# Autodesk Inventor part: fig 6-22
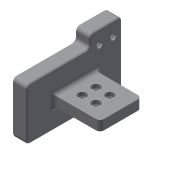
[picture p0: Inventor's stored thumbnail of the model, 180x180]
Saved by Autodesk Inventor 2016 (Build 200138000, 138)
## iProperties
Created: 2004-05
Part Number: fig 6-22
Document SubType Name: Modeling
Designer: CADCIM Technologies
Manufacturer: Standard
Standards Organization: Custom
Density: 1 g/cm^3
Material: Generic
Appearance: Default
Author: CADCIM Technologies
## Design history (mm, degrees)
node "Sketch1"
sketch "Sketch2"
  geometry: L1 (0, 0)-(0, 26.557); L2 (0, 26.557)-(31.986, 26.557); L3 (31.986, 26.557)-(31.986, 32.916); L4 (31.986, 32.916)-(48.42, 32.916); L5 (48.42, 32.916)-(48.42, 0); L6 (48.42, 0)-(0, 0)
  constraints: 12 end point, 4 parallel, 1 perpendicular, 1 vertical
extrude "Extrusion1" new body sketch "Sketch2" distance "d0" = 7.5; taper "d1" = 0 deg
workplane "Work Plane1"
sketch "Sketch3"
  geometry: L1 (7.5, 35.088)-(30.78, 35.088); L2 (30.78, 35.088)-(30.78, 13.871); L3 (30.78, 13.871)-(7.5, 13.871); L4 (7.5, 31.986)-(7.5, 48.42) reference; L5 (7.5, 0)-(7.5, 31.986) reference
  constraints: 6 end point, 2 point on line, 1 horizontal, 1 parallel, 1 perpendicular
extrude "Extrusion2" join sketch "Sketch3" distance "d3" = 5; taper "d4" = 0 deg
fillet "Fillet2" dims "d7" = 2
fillet "Fillet3" dims "d8" = 2
hole "Hole1" diameter "d11" = 3; stored, may be unused: countersink angle "d15" = 90 deg, drill point angle "d17" = 118 deg; dims "d9" = 7, "d10" = 16, "d12" = 6, "d13" = 4, "d14" = 2, "d16" = 8
pattern_linear "Rectangular Pattern1" dims "d20" = 7, "d23" = 7
hole "Hole2" diameter "d26" = 2; stored, may be unused: countersink angle "d30" = 90 deg, drill point angle "d32" = 118 deg; dims "d24" = 5, "d25" = 7, "d27" = 6, "d28" = 3, "d29" = 1, "d31" = 8
pattern_linear "Rectangular Pattern2" dims "d35" = 7
fillet "Fillet4" dims "d36" = 2
fillet "Fillet5" dims "d37" = 1
fillet "Fillet6" dims "d38" = 1
body "Solid1"
other parameters: "d2" = -11
